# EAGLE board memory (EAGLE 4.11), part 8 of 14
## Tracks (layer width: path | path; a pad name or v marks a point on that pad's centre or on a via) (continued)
GND  (via drill 0.61) (continued)
  Bottom 0.635: B38.U2 29.84,288.93 26.04,288.93 24.13,290.83 21.59,290.83 20.32,289.56 17.78,289.56 B39.U2 | B38.N2 26.67,304.8 22.86,304.8 20.95,302.9 19.05,302.9 17.78,304.17 14.61,304.17 B39.N2 | B31.H2 119.38,321.31 120.02,321.95 124.46,321.95 125.09,322.58 127,322.58 128.91,320.68 131.44,320.68 B30.H2 | B35.V2 65.41,285.12 66.67,283.85 76.2,283.85 77.47,285.12 B34.V2 | A29.P2 144.78,370.84 145.41,370.21 149.86,370.21 151.13,368.94 153.67,368.94 A28.R2 | A20.U2 259.08,358.14 259.71,357.5 264.16,357.5 264.8,356.87 266.7,356.87 267.97,358.14 271.14,358.14 A19.U2 | B19.N2 268.61,304.17 269.24,303.53 273.69,303.53 274.32,302.9 v276.23,302.9 276.86,302.9 278.13,304.17 280.67,304.17 B18.N2 | B19.U2 271.78,288.29 272.42,287.66 v276.23,287.66 276.86,287.66 277.5,287.02 279.4,287.02 280.67,288.29 283.85,288.29 B18.U2 | B18.H2 283.85,320.04 283.21,319.41 278.76,319.41 278.13,318.77 275.59,318.77 274.32,320.04 271.78,320.04 B19.H2 | D03.C2 474.35,196.22 469.9,196.22 468.63,194.94 466.09,194.94 464.82,196.22 462.28,196.22 D04.C2 461.64,196.85 459.11,196.85 457.2,194.94 455.3,194.94 454.66,195.58 450.21,195.58 449.58,196.22 D05.C2 448.94,196.22 448.31,195.58 443.87,195.58 443.23,194.94 442.6,194.94 440.69,196.85 436.88,196.85 D06.C2 436.25,196.22 435.61,195.58 431.17,195.58 430.53,194.94 427.99,194.94 426.72,196.22 424.18,196.22 D07.C2 423.55,196.22 420.37,196.22 419.1,194.94 417.19,194.94 415.29,196.85 411.48,196.85 D08.C2 410.85,196.85 407.67,196.85 405.76,194.94 404.5,194.94 402.59,196.85 398.78,196.85 D09.C2 398.14,196.85 394.33,196.85 392.43,194.94 391.8,194.94 389.89,196.85 386.08,196.85 D10.C2 385.44,196.85 382.9,196.85 381,194.94 379.1,194.94 377.19,196.85 373.38,196.85 D11.C2 372.75,196.85 368.94,196.85 367.03,194.94 366.39,194.94 364.49,196.85 360.68,196.85 D12.C2 360.05,196.85 357.5,196.85 355.6,194.94 353.69,194.94 351.79,196.85 347.98,196.85 D13.C2 347.35,196.85 344.81,196.85 342.9,194.94 341,194.94 339.09,196.85 335.28,196.85 D14.C2 334.64,196.85 332.11,196.85 330.2,194.94 328.3,194.94 326.39,196.85 322.58,196.85 D15.C2 321.94,196.85 318.13,196.85 316.23,194.94 315.6,194.94 313.69,196.85 309.88,196.85 D16.C2 309.25,196.85 306.7,196.85 304.8,194.94 302.89,194.94 302.26,195.58 297.81,195.58 297.18,196.22 D17.C2 296.55,196.22 295.91,195.58 291.46,195.58 290.83,194.94 290.19,194.94 288.29,196.85 284.48,196.85 D18.C2 283.85,196.85 280.04,196.85 278.13,194.94 275.59,194.94 274.32,196.22 271.78,196.22 D19.C2 271.14,197.48 267.97,197.48 266.7,198.75 262.89,198.75 262.25,198.12 259.71,198.12 259.08,197.48 D20.C2 258.44,196.22 257.81,195.58 253.37,195.58 252.73,194.94 252.09,194.94 250.82,196.22 246.38,196.22 D21.C2 245.75,196.22 242.57,196.22 241.3,194.94 239.4,194.94 237.49,196.85 233.68,196.85 D22.C2 233.04,197.48 229.87,197.48 228.6,198.75 226.69,198.75 224.79,196.85 220.98,196.85 D23.C2 220.34,197.48 217.17,197.48 215.9,198.75 214,198.75 212.09,196.85 208.28,196.85 D24.C2 207.65,197.48 204.47,197.48 203.2,198.75 201.29,198.75 199.39,196.85 195.58,196.85 D25.C2 194.94,197.48 191.77,197.48 190.5,198.75 188.59,198.75 186.69,196.85 182.88,196.85 D26.C2 182.25,197.48 179.07,197.48 177.8,198.75 175.9,198.75 173.99,196.85 170.18,196.85 D27.C2 169.54,197.48 168.91,198.12 164.47,198.12 163.83,198.75 161.29,198.75 160.02,197.48 157.48,197.48 D28.C2 156.84,196.85 154.31,196.85 152.4,194.94 150.5,194.94 149.86,195.58 145.41,195.58 144.78,196.22 D29.C2 144.15,196.85 140.34,196.85 138.43,194.94 137.79,194.94 135.89,196.85 132.08,196.85 D30.C2 131.44,196.22 130.81,195.58 126.36,195.58 125.73,194.94 123.19,194.94 121.92,196.22 119.38,196.22 D31.C2 118.75,196.22 115.57,196.22 114.3,194.94 112.39,194.94 111.76,195.58 107.31,195.58 106.68,196.22 D32.C2 106.05,196.22 105.41,195.58 100.97,195.58 100.33,194.94 97.79,194.94 96.52,196.22 93.98,196.22 D33.C2 93.34,196.22 92.71,195.58 88.27,195.58 87.63,194.94 85.09,194.94 83.82,196.22 81.28,196.22 D34.C2 80.64,196.22 80.01,195.58 75.56,195.58 74.93,194.94 72.39,194.94 71.12,196.22 68.58,196.22 D35.C2 67.94,196.22 67.31,195.58 62.87,195.58 62.23,194.94 59.69,194.94 58.42,196.22 55.88,196.22 D36.C2 55.24,196.22 54.61,195.58 50.16,195.58 49.53,194.94 46.99,194.94 45.72,196.22 43.18,196.22 D37.C2 42.55,197.48 38.1,197.48 36.83,198.75 34.29,198.75 33.66,198.12 29.21,198.12
  Bottom 0.635: D10.H2 386.08,183.51 386.71,182.88 391.16,182.88 391.8,182.25 393.06,182.25 394.97,184.15 398.14,184.15 D09.H2 | C38.N2 27.3,237.49 31.75,237.49 33.02,236.22 35.56,236.22 36.83,237.49 39.37,237.49 C37.N2 | C22.U2 233.04,222.25 231.14,222.25 230.5,222.88 230.5,224.79 C22.T2 | v355.6,98.42 360.05,98.42 E12.P2 | F03.C2 474.35,59.69 473.71,59.05 469.26,59.05 468.63,58.42 466.09,58.42 464.82,59.69 462.28,59.69 F04.C2 461.64,59.69 461.01,59.05 456.56,59.05 455.93,58.42 453.39,58.42 452.12,59.69 449.58,59.69 F05.C2 448.94,59.69 448.31,59.05 443.87,59.05 443.23,58.42 440.69,58.42 439.42,59.69 436.88,59.69 F06.C2 436.25,60.96 431.8,60.96 430.53,62.23 427.99,62.23 426.72,60.96 424.18,60.96 F07.C2 423.55,60.96 422.91,61.59 418.46,61.59 417.83,62.23 415.29,62.23 414.02,60.96 411.48,60.96 F08.C2 410.85,60.96 410.21,61.59 405.76,61.59 405.13,62.23 402.59,62.23 401.32,60.96 398.78,60.96 F09.C2 398.14,59.69 397.51,59.05 393.06,59.05 392.43,58.42 389.89,58.42 388.62,59.69 386.08,59.69 F10.C2 385.44,59.69 382.27,59.69 381,58.42 379.1,58.42 377.19,60.33 373.38,60.33 F11.C2 372.75,59.69 369.57,59.69 368.3,58.42 366.39,58.42 364.49,60.33 360.68,60.33 F12.C2 360.05,59.69 356.87,59.69 355.6,58.42 353.69,58.42 351.79,60.33 347.98,60.33 F13.C2 347.35,60.33 343.54,60.33 341.63,58.42 341,58.42 339.09,60.33 335.28,60.33 F14.C2 334.64,60.33 330.83,60.33 328.93,58.42 327.66,58.42 325.75,60.33 322.58,60.33 F15.C2 321.94,60.33 318.13,60.33 316.23,62.23 314.96,62.23 313.06,60.33 309.88,60.33 F16.C2 309.25,60.96 308.61,61.59 304.17,61.59 303.53,62.23 302.26,62.23 300.36,60.33 297.18,60.33 F17.C2 296.55,60.96 293.37,60.96 292.1,62.23 290.19,62.23 288.29,60.33 284.48,60.33 F18.C2 283.85,60.96 283.21,61.59 278.76,61.59 278.13,62.23 276.86,62.23 274.95,60.33 271.78,60.33 F19.C2 271.14,60.33 267.33,60.33 265.43,58.42 262.89,58.42 261.62,59.69 259.08,59.69 F20.C2 258.44,60.33 254.63,60.33 252.73,58.42 250.19,58.42 248.92,59.69 246.38,59.69 F21.C2 245.75,59.69 245.11,59.05 240.66,59.05 240.03,58.42 237.49,58.42 236.22,59.69 233.68,59.69 F22.C2 233.04,60.33 229.24,60.33 223.52,54.61 220.98,54.61 F23.E2
  Bottom 0.635: F32.N2 103.5,32.38 104.14,33.02 108.58,33.02 113.03,37.46 115.57,37.46 F31.L2 | F31.C2 118.75,60.33 115.57,60.33 113.67,62.23 112.39,62.23 111.76,61.59 107.31,61.59 106.68,60.96 F32.C2 106.05,60.96 105.41,61.59 100.97,61.59 100.33,62.23 97.79,62.23 96.52,60.96 93.98,60.96 F33.C2 93.34,59.69 90.17,59.69 88.9,58.42 87,58.42 86.36,59.05 81.92,59.05 81.28,59.69 F34.C2 80.64,59.69 80.01,59.05 75.56,59.05 74.93,58.42 73.66,58.42 71.75,60.33 68.58,60.33 F35.C2 67.94,60.96 67.31,61.59 62.87,61.59 62.23,62.23 59.69,62.23 58.42,60.96 55.88,60.96 F36.C2 55.24,60.96 54.61,61.59 50.16,61.59 49.53,62.23 46.99,62.23 45.72,60.96 43.18,60.96 F37.C2 42.55,59.69 41.91,59.05 37.47,59.05 36.83,58.42 34.29,58.42 33.02,59.69 30.48,59.69 F38.C2 29.84,60.96 29.21,61.59 24.77,61.59 24.13,62.23 21.59,62.23 20.32,60.96 17.78,60.96 F39.C2 17.14,60.96 13.97,60.96 12.7,62.23 10.79,62.23 10.16,61.59 5.71,61.59 5.08,60.96 F40.C2 | F30.F2 128.27,50.16 127.64,49.53 123.83,49.53 119.38,45.09 116.2,45.09 F31.J2 | F23.C2 220.34,59.69 217.17,59.69 215.9,58.42 214,58.42 213.36,59.05 208.91,59.05 208.28,59.69 F24.C2 207.65,59.69 204.47,59.69 203.2,58.42 201.29,58.42 199.39,60.33 195.58,60.33 F25.C2 194.94,60.96 191.77,60.96 190.5,62.23 188.59,62.23 186.69,60.33 182.88,60.33 F26.C2 182.25,60.96 181.61,61.59 177.16,61.59 176.53,62.23 173.99,62.23 172.72,60.96 170.18,60.96 F27.C2 169.54,60.96 166.37,60.96 165.1,62.23 163.19,62.23 162.56,61.59 158.12,61.59 157.48,60.96 F28.C2 156.84,60.96 153.67,60.96 152.4,62.23 150.5,62.23 148.59,60.33 144.78,60.33 F29.C2
  Bottom 0.635: E03.C2 474.35,129.54 473.71,128.91 469.26,128.91 468.63,128.27 468,128.27 466.09,130.18 462.28,130.18 E04.C2 461.64,130.81 458.47,130.81 457.2,132.08 455.3,132.08 453.39,130.18 449.58,130.18 E05.C2 448.94,130.81 445.77,130.81 444.5,132.08 442.6,132.08 440.69,130.18 436.88,130.18 E06.C2 436.25,130.81 433.07,130.81 431.8,132.08 429.89,132.08 427.99,130.18 424.18,130.18 E07.C2 423.55,130.81 422.91,131.44 418.46,131.44 417.83,132.08 416.56,132.08 414.65,130.18 411.48,130.18 E08.C2 410.85,130.18 407.67,130.18 405.76,128.27 404.5,128.27 403.86,128.91 399.42,128.91 398.78,129.54 E09.C2 398.14,130.81 394.97,130.81 393.7,132.08 391.8,132.08 389.89,130.18 386.08,130.18 E10.C2 385.44,130.81 382.27,130.81 381,132.08 379.1,132.08 377.19,130.18 373.38,130.18 E11.C2 372.75,130.81 369.57,130.81 368.3,132.08 366.39,132.08 364.49,130.18 360.68,130.18 E12.C2 360.05,130.81 356.87,130.81 355.6,132.08 353.69,132.08 351.79,130.18 347.98,130.18 E13.C2 347.35,130.81 344.17,130.81 342.9,132.08 341,132.08 339.09,130.18 335.28,130.18 E14.C2 334.64,130.81 334.01,131.44 329.56,131.44 328.93,132.08 326.39,132.08 325.12,130.81 322.58,130.81 E15.C2 321.94,130.81 318.77,130.81 317.5,132.08 315.6,132.08 313.69,130.18 309.88,130.18 E16.C2 309.25,130.81 306.07,130.81 304.8,132.08 302.89,132.08 300.99,130.18 297.18,130.18 E17.C2 296.55,130.81 293.37,130.81 292.1,132.08 290.19,132.08 288.29,130.18 284.48,130.18 E18.C2 283.85,130.81 280.67,130.81 279.4,132.08 277.5,132.08 275.59,130.18 271.78,130.18 E19.C2 271.14,130.81 267.97,130.81 266.7,132.08 264.8,132.08 262.89,130.18 259.08,130.18 E20.C2 258.44,130.81 255.27,130.81 254,132.08 252.09,132.08 250.19,130.18 246.38,130.18 E21.C2 245.75,130.81 242.57,130.81 241.3,132.08 239.4,132.08 237.49,130.18 233.68,130.18 E22.C2 233.04,130.81 229.87,130.81 228.6,132.08 226.69,132.08 224.79,130.18 220.98,130.18 E23.C2 220.34,130.81 217.17,130.81 215.9,132.08 214,132.08 212.09,130.18 208.28,130.18 E24.C2 207.65,130.18 203.84,130.18 201.93,132.08 200.66,132.08 198.75,130.18 195.58,130.18 E25.C2 194.94,130.81 191.77,130.81 190.5,132.08 188.59,132.08 186.69,130.18 182.88,130.18 E26.C2 182.25,130.81 181.61,131.44 177.16,131.44 176.53,132.08 175.26,132.08 173.35,130.18 170.18,130.18 E27.C2 169.54,130.18 165.74,130.18 163.83,128.27 161.29,128.27 160.02,129.54 157.48,129.54 E28.C2 156.84,130.81 156.21,131.44 151.76,131.44 151.13,132.08 148.59,132.08 147.32,130.81 144.78,130.81 E29.C2 144.15,130.81 143.51,131.44 139.06,131.44 138.43,132.08 135.89,132.08 134.62,130.81 132.08,130.81 E30.C2
  Bottom 0.635: D09.U2 398.14,152.4 394.33,152.4 392.43,150.5 391.16,150.5 389.25,152.4 386.08,152.4 D10.U2 | D09.N2 394.97,167.64 394.33,167 389.89,167 389.25,166.37 387.99,166.37 386.08,168.28 382.9,168.28 D10.N2 | D40.C2 5.08,197.48 7.62,197.48 8.89,198.75 11.43,198.75 12.06,198.12 16.51,198.12 17.14,197.48 D39.C2 17.78,197.48 20.32,197.48 21.59,198.75 24.13,198.75 24.77,198.12 29.21,198.12 | 29.21,198.12 29.84,197.48 D38.C2 | E40.N2 1.91,100.96 5.08,100.96 9.53,96.52 13.34,96.52 13.97,95.88 E39.R2 14.61,95.88 17.78,95.88 23.5,101.6 26.67,101.6 E38.N2 | E32.U2 106.68,85.09 107.31,84.45 111.76,84.45 112.39,83.82 114.3,83.82 115.57,85.09 118.75,85.09 E31.U2 119.38,85.09 120.02,84.45 124.46,84.45 125.09,83.82 127,83.82 128.27,85.09 131.44,85.09 E30.U2 | E32.N2 103.5,100.96 104.14,100.33 108.58,100.33 109.22,99.69 111.76,99.69 113.03,100.96 115.57,100.96 E31.N2 | F39.N2 14.61,31.12 15.24,30.48 19.68,30.48 20.32,29.84 22.86,29.84 24.13,31.12 26.67,31.12 F38.N2 27.3,31.12 30.48,31.12 31.75,29.84 33.66,29.84 34.29,30.48 38.73,30.48 39.37,31.12 F37.N2 | E37.C2 43.18,130.81 45.72,130.81 46.99,132.08 49.53,132.08 50.16,131.44 54.61,131.44 55.24,130.81 E36.C2 55.88,130.81 58.42,130.81 59.69,132.08 62.23,132.08 62.87,131.44 67.31,131.44 67.94,130.81 E35.C2 68.58,130.81 71.12,130.81 72.39,132.08 74.93,132.08 75.56,131.44 80.01,131.44 80.64,130.81 E34.C2 81.28,130.81 83.82,130.81 85.09,132.08 87.63,132.08 88.27,131.44 92.71,131.44 93.34,130.81 E33.C2 93.98,130.81 96.52,130.81 97.79,132.08 100.33,132.08 100.97,131.44 105.41,131.44 106.05,130.81 E32.C2 106.68,130.81 109.22,130.81 110.49,132.08 113.03,132.08 114.94,130.18 118.75,130.18 E31.C2
IAC+CMA  (via drill 0.61)
  Top 0.254: v223.52,327.03 225.43,325.12 v225.43,278.77 | v276.23,278.13 276.23,22.86 271.78,18.41 271.78,16.51 F19.U2 | v337.19,33.02 336.55,32.38 336.55,17.78 335.28,16.51 F14.U2
  Route2 0.254: v223.52,327.03 220.98,327.03 B23.E2
  Bottom 0.254: F19.U2 271.78,16.51 276.23,16.51 277.5,17.78 286.38,17.78 287.02,17.14 289.56,17.14 290.19,17.78 299.08,17.78 299.72,17.14 302.26,17.14 302.89,17.78 311.79,17.78 312.42,17.14 314.96,17.14 315.6,17.78 324.49,17.78 325.12,17.14 327.66,17.14 328.3,17.78 329.56,17.78 330.83,16.51 334.64,16.51 F14.U2 | v225.43,278.77 275.59,278.77 v276.23,278.13 | v337.19,33.02 332.74,33.02 332.11,32.38 F14.N2
IF0  (via drill 0.61)
  Top 0.254: v122.56,67.94 122.56,78.1 116.84,83.82 116.84,87.63 116.2,88.27 E31.T2 | v258.44,39.37 266.7,31.12 v266.7,15.88 | v328.93,12.06 330.83,10.16 v330.83,9.52
  Route2 0.254: v122.56,67.94 123.19,68.58 133.99,68.58 143.51,59.05 149.86,59.05 153.67,55.25 162.56,55.25 163.19,55.88 172.09,55.88 172.72,55.25 175.26,55.25 175.9,55.88 184.78,55.88 185.42,55.25 187.96,55.25 188.59,55.88 197.49,55.88 201.29,52.07 210.19,52.07 210.82,52.7 213.36,52.7 216.53,49.53 222.88,49.53 229.87,42.55 238.76,42.55 239.4,43.18 246.38,43.18 250.19,39.37 v258.44,39.37
  Route3 0.254: v330.83,9.52 332.74,7.62 347.35,7.62 347.98,6.98 351.15,6.98 353.06,8.89 370.2,8.89 371.48,10.16 386.08,10.16 386.08,8.89 386.71,8.25 v386.71,7.62
  Bottom 0.254: v266.7,15.88 267.97,14.61 276.86,14.61 280.67,10.79 288.93,10.79 292.74,14.61 302.26,14.61 302.89,13.97 311.79,13.97 312.42,14.61 314.96,14.61 318.77,10.79 327.02,10.79 328.3,12.06 v328.93,12.06 | v386.71,7.62 387.99,6.35 393.7,6.35 394.33,6.98 401.32,6.98 405.13,10.79 435.61,10.79 445.77,20.95 454.66,20.95 458.47,17.14 467.36,17.14 468,17.78 476.88,17.78 477.52,17.14 479.43,17.14 498.48,36.2 498.48,39.37 491.49,39.37 487.05,43.82 484.5,43.82 F02.J2
IF1  (via drill 0.61)
  Top 0.254: v365.12,22.23 365.12,17.14 v354.96,6.98 | v336.55,4.44 330.83,4.44 327.02,0.63 288.93,0.63 v288.93,28.58 | v119.38,62.87 116.2,66.04 116.2,81.91 E31.V2
  Route2 0.254: v478.79,45.72 478.15,46.36 470.54,46.36 466.73,42.55 456.56,42.55 455.93,43.18 454.66,43.18 448.31,36.83 440.69,36.83 440.06,36.2 431.17,36.2 430.53,36.83 427.99,36.83 424.18,33.02 415.29,33.02 408.94,39.37 402.59,39.37 398.78,43.18 391.16,43.18 387.35,39.37 381,39.37 v376.56,34.92 | v354.96,6.98 352.43,4.44 341,4.44 339.73,5.71 337.82,5.71 v336.55,4.44 | v265.43,24.13 262.89,24.13 262.25,23.49 253.37,23.49 249.56,27.3 240.66,27.3 236.85,23.49 234.31,23.49 231.14,26.67 224.79,26.67 224.16,27.3 219.71,27.3 219.07,26.67 212.09,26.67 211.46,27.3 202.56,27.3 198.75,23.49 197.49,23.49 194.31,26.67 186.69,26.67 182.88,30.48 173.99,30.48 170.18,26.67 161.29,26.67 160.66,27.3 151.76,27.3 151.13,26.67 149.86,26.67 120.65,55.88 120.65,62.87 v119.38,62.87
  Route3 0.254: v376.56,34.92 365.12,23.49 v365.12,22.23
  Bottom 0.254: v478.79,45.72 485.77,45.72 487.05,46.99 F02.H2 | v288.93,28.58 287.65,29.84 283.21,29.84 280.04,26.67 275.59,26.67 274.95,27.3 272.42,27.3 269.24,24.13 v265.43,24.13
IF2  (via drill 0.61)
  Top 0.254: v163.19,393.7 179.07,409.58 179.07,421 179.71,421.64 306.07,421.64 v306.07,415.93
  Route2 0.254: v306.07,415.93 319.4,415.93 321.94,413.39 393.7,413.39 v396.24,415.93 | v506.1,249.56 504.82,248.28 504.82,67.94 499.11,67.94 484.5,53.34 484.5,51.44 F02.F2
  Route3 0.254: v114.3,158.75 114.3,151.76 107.95,145.41 107.95,121.92 104.78,118.74 104.78,90.8 103.5,89.53 E32.T2 | v122.56,165.1 123.83,166.37 123.83,203.2 122.56,204.47 122.56,217.17 123.83,218.44 123.83,316.87 127,320.04 127,356.24 163.19,392.43 v163.19,393.7
  Bottom 0.254: v114.3,158.75 114.3,163.83 121.28,163.83 v122.56,165.1 | v396.24,415.93 396.88,415.29 407.04,415.29 407.67,414.66 437.51,414.66 438.15,415.29 440.06,415.29 442.6,412.75 481.33,412.75 504.82,389.25 504.82,297.81 503.56,296.55 503.56,294 504.82,292.74 504.82,252.73 506.1,251.46 v506.1,249.56
INH1  (via drill 0.61)
  Top 0.254: v102.23,284.48 104.78,281.94 104.78,264.16 107.95,260.99 107.95,255.91 111.12,252.73 v111.12,244.47 | v156.84,239.39 156.21,238.76 156.21,238.12 158.75,235.59 158.75,229.23 161.93,226.06 v161.93,217.17
  Route2 0.254: v102.23,284.48 99.06,287.66 90.81,287.66 90.81,291.47 B33.T2 | v161.93,217.17 163.83,215.26 219.07,215.26 220.98,217.17 229.24,217.17 229.87,217.81 234.95,217.81 236.85,215.9 237.49,215.9 243.21,221.61 245.75,221.61 C21.U2
  Bottom 0.254: v111.12,244.47 113.67,244.47 118.11,240.03 120.65,240.03 121.28,240.66 123.83,240.66 125.09,239.39 132.72,239.39 133.99,240.66 136.53,240.66 137.79,239.39 146.69,239.39 147.32,240.03 149.86,240.03 150.5,239.39 v156.84,239.39
INHIBIT  (via drill 0.61)
  Top 0.254: v101.6,43.18 98.42,46.36 98.42,81.91 101.6,85.09 101.6,150.5 103.5,152.4 v103.5,153.67
  Route2 0.254: v103.5,153.67 121.92,172.09 123.83,172.09 128.27,176.53 134.62,176.53 138.43,180.34 140.97,180.34 D29.J2
  Bottom 0.254: v101.6,43.18 106.05,43.18 106.05,46.99 F32.H2
INS  (via drill 0.61)
  Top 0.254: v120.65,254 120.65,283.85 113.67,290.83 v113.67,294
  Route2 0.254: v81.28,175.89 85.09,179.7 93.34,179.7 99.69,186.06 108.58,186.06 109.22,185.42 109.86,185.42 v118.75,194.31 | v155.57,386.08 156.21,385.45 162.56,385.45 163.19,386.08 172.09,386.08 172.72,385.45 174.62,385.45 180.97,391.8 186.06,391.8 191.77,397.51 191.77,399.42 A25.D2
  Route3 0.254: v118.75,194.31 120.65,196.22 120.65,215.9 118.11,218.44 118.11,219.07 120.65,221.61 120.65,237.49 119.38,238.76 119.38,239.39 120.65,240.66 v120.65,254 | v113.67,294 117.47,297.81 117.47,341.63 126.36,350.52 126.36,356.87 133.35,363.86 133.35,369.57 149.86,386.08 v155.57,386.08
  Bottom 0.254: v81.28,175.89 74.93,175.89 62.23,163.19 61.59,163.19 60.96,163.83 52.07,163.83 41.27,153.03 40.01,154.31 36.2,154.31 35.56,153.67 28.57,153.67 27.3,154.94 D38.T2
IO_CLEAR  (via drill 0.61)
  Top 0.254: v277.5,57.15 279.4,55.25 279.4,27.3 280.67,26.03 F18.R2 | v295.91,76.2 295.27,75.56 295.27,61.59 v293.37,59.69 | v12.7,342.9 12.7,287.66 13.97,286.39 B39.V2 | v208.28,347.98 v208.28,351.16 | v295.27,367.67 295.27,379.1 294,380.37 A17.L2 | v170.18,154.94 170.18,156.84 171.45,158.11 171.45,167.64 168.28,170.81 v168.28,190.5 | v170.18,243.84 170.18,245.75 171.45,247.01 171.45,261.62 168.28,264.8 168.28,291.47 171.45,294.64 v171.45,306.07
  Route2 0.254: v379.1,88.9 370.84,80.64 350.52,80.64 349.25,79.38 312.42,79.38 311.15,78.1 297.81,78.1 v295.91,76.2 | v214.63,79.38 217.81,76.2 246.38,76.2 259.08,63.5 259.71,63.5 264.8,58.42 267.33,58.42 267.97,57.79 F19.D2
  Route3 0.254: v379.1,88.9 381,90.8 381,109.22 382.27,109.22 383.54,110.49 385.44,110.49 E10.K2 | v290.19,350.52 290.83,351.16 290.83,356.87 292.1,358.14 292.1,364.49 v295.27,367.67 | v198.75,79.38 196.85,81.28 v196.85,81.91 | v179.07,91.44 174.62,95.88 174.62,150.5 v170.18,154.94 | v168.28,190.5 168.28,218.44 171.45,221.61 171.45,242.57 v170.18,243.84 | v171.45,306.07 171.45,346.08 172.09,346.71 v172.09,347.98
  Bottom 0.254: F19.D2 268.61,57.79 269.88,59.05 275.59,59.05 v277.5,57.15 279.4,59.05 287.65,59.05 288.29,58.42 292.1,58.42 v293.37,59.69 | v12.7,342.9 98.42,342.9 102.23,346.71 133.35,346.71 133.99,346.08 166.37,346.08 168.28,347.98 v172.09,347.98 183.51,347.98 184.15,348.62 207.65,348.62 v208.28,347.98 | v208.28,351.16 208.91,351.79 210.82,351.79 212.09,350.52 223.52,350.52 224.16,351.16 247.01,351.16 248.28,349.89 249.56,349.89 250.19,350.52 269.88,350.52 271.14,349.25 288.93,349.25 v290.19,350.52 | v198.75,79.38 v214.63,79.38 | v196.85,81.91 194.94,83.82 186.69,83.82 v179.07,91.44
IO_INT  (via drill 0.61)
  Route2 0.254: v11.43,149.22 11.43,150.5 12.7,151.76 12.7,175.26 v14.61,177.16
  Route3 0.254: v11.43,149.22 9.53,147.32 9.53,125.09 6.35,121.92 6.35,43.18 5.08,41.91 F40.K2 | v14.61,177.16 15.88,178.44 15.88,224.79 22.23,231.14 22.23,276.23 25.4,279.4 25.4,299.09 28.57,302.26 28.57,344.81 22.23,351.16 22.23,368.3 23.5,369.57 19.05,374.02 19.05,391.16 8.26,401.96 1.91,401.96 1.91,400.69 A40.D2
ION  (via drill 0.61)
  Top 0.254: v23.5,127 25.4,128.91 25.4,140.97 24.13,142.24 24.13,150.5 25.4,151.76 25.4,156.84 27.94,159.38 27.94,160.66 28.57,161.29 v28.57,168.91 | v328.93,74.29 327.02,72.39 327.02,57.79 v330.2,54.61
  Route2 0.254: v328.93,74.29 331.47,76.83 350.52,76.83 351.15,77.47 353.69,77.47 354.33,76.83 377.82,76.83 379.73,78.74 405.76,78.74 408.31,81.28 409.57,81.28 409.57,87.63 423.55,101.6 423.55,104.14 E07.M2 | v330.2,54.61 325.75,59.05 325.12,59.05 321.94,55.88 316.23,55.88 313.06,59.05 310.51,59.05 307.98,56.52 307.98,50.16 v309.25,50.16 | v306.7,36.2 306.07,36.83 305.44,36.83 298.45,43.82 297.18,43.82 v296.55,43.18 | v283.85,38.1 282.57,39.37 279.4,39.37 275.59,35.56 273.05,35.56 272.42,36.2 266.06,36.2 259.08,43.18 250.19,43.18 249.56,42.55 248.28,42.55 245.11,45.72 237.49,45.72 231.14,52.07 226.69,52.07 224.16,54.61 222.25,54.61 218.44,58.42 212.09,58.42 211.46,59.05 202.56,59.05 201.93,58.42 199.39,58.42 195.58,62.23 186.69,62.23 182.88,58.42 173.99,58.42 170.18,62.23 161.29,62.23 160.66,61.59 153.03,61.59 v151.13,63.5
  Route3 0.254: v17.78,57.15 19.05,58.42 19.05,114.93 22.23,118.11 22.23,125.73 v23.5,127 | v28.57,168.91 28.57,179.07 27.3,180.34 D38.J2 | v309.25,50.16 311.15,48.26 311.15,40.64 v306.7,36.2 | v296.55,43.18 288.29,43.18 288.29,42.55 v283.85,38.1
  Bottom 0.254: 15.88,55.25 v17.78,57.15 | 15.88,55.25 3.81,43.18 1.91,43.18 1.91,38.73 F40.L2 | v151.13,63.5 149.86,63.5 147.96,61.59 141.6,61.59 135.25,55.25 127.64,55.25 125.09,57.79 119.38,52.07 110.49,52.07 109.86,52.7 100.97,52.7 100.33,52.07 97.79,52.07 93.98,55.88 85.09,55.88 84.45,55.25 75.56,55.25 71.75,59.05 62.87,59.05 59.05,55.25 50.16,55.25 49.53,55.88 46.99,55.88 43.18,52.07 34.29,52.07 30.48,55.88 21.59,55.88 20.95,55.25 15.88,55.25
IOP1  (via drill 0.61)
  Top 0.254: A40.T2 1.27,362.59 1.27,367.67 A40.R2 | v17.14,299.09 15.88,300.36 15.88,312.42 17.14,313.69 B39.K2 | v11.43,45.72 9.53,45.72 9.53,198.75 12.7,201.93 12.7,278.77 v11.43,280.04 | v415.93,5.08 v415.93,39.37 | v81.92,4.44 55.24,31.12 52.7,31.12 F36.N2 | v10.79,354.97 15.88,349.89 15.88,333.38 v14.61,332.11
  Route3 0.254: A40.J2 1.91,386.72 3.17,385.45 3.17,370.21 1.91,368.94 A40.R2
  Bottom 0.254: v17.14,299.09 8.26,290.2 5.71,290.2 5.08,289.56 B40.U2 5.08,288.29 5.08,286.39 v11.43,280.04 | v11.43,45.72 17.78,45.72 21.59,49.53 30.48,49.53 46.99,33.02 51.44,33.02 52.07,32.38 F36.N2 | v415.93,39.37 422.27,39.37 423.55,40.64 F07.K2 | v415.93,5.08 396.24,5.08 395.61,4.44 375.92,4.44 374.65,3.17 341,3.17 339.73,4.44 339.09,4.44 337.19,2.54 290.19,2.54 288.29,4.44 283.21,4.44 282.57,5.08 281.94,5.08 279.4,2.54 225.43,2.54 222.88,5.08 208.91,5.08 207.01,3.17 201.93,3.17 201.29,3.81 197.49,3.81 195.58,1.9 84.45,1.9 v81.92,4.44 | v10.79,354.97 5.71,360.05 3.17,360.05 1.91,361.31 A40.T2 | v14.61,332.11 19.68,327.03 19.68,325.12 15.88,321.31 15.88,314.96 17.14,314.96 B39.K2
IOP2  (via drill 0.61)
  Top 0.254: v377.82,368.94 374.65,372.11 374.65,388.62 373.38,389.89 A11.H2 | 3.17,294 1.91,292.74 B40.T2 | 3.17,306.71 3.17,379.1 1.91,380.37 A40.L2 1.91,381.64 1.91,383.54 6.35,387.99 6.35,407.04 6.99,407.67 6.99,415.93 v45.09,415.93 | 3.17,306.71 3.17,294 | v57.15,273.05 57.15,164.47 55.88,163.19 55.88,159.38 D36.S2 | v5.08,274.96 3.17,276.86 3.17,294 | 3.17,306.71 v1.91,306.71 | v331.47,412.12 331.47,412.75 347.98,412.75 365.12,395.61 365.12,387.99 369.57,387.99 A11.J2 | v261.62,417.2 257.81,417.2 254,421 180.34,421 v180.34,419.74
  Route2 0.254: v314.96,406.4 309.88,401.32 300.99,401.32 297.18,405.13 290.83,405.13 281.94,414.02 267.97,414.02 263.52,418.47 262.89,418.47 v261.62,417.2 | v180.34,419.74 177.8,417.2 150.5,417.2 149.22,415.93 v147.96,415.93
  Route3 0.254: v331.47,412.12 320.68,412.12 v314.96,406.4
  Bottom 0.254: A11.J2 370.2,387.99 372.11,389.89 372.75,389.89 A11.H2 | 407.04,360.68 407.04,358.78 407.67,358.14 407.67,356.24 A08.V2 | 407.04,360.68 408.94,360.68 410.85,362.59 410.85,364.49 A08.S2 | v377.82,368.94 380.37,366.4 391.16,366.4 391.8,367.03 399.42,367.03 405.76,360.68 407.04,360.68 | v57.15,273.05 57.15,274.96 v5.08,274.96 | v1.91,306.71 8.26,306.71 8.89,306.07 15.88,306.07 17.14,307.34 B39.M2 | v147.96,415.93 v45.09,415.93
IOP4  (via drill 0.61)
  Top 0.254: 34.92,332.11 v36.83,330.2 | 34.92,351.79 34.92,377.83 33.66,379.1 31.75,379.1 31.75,377.19 30.48,375.92 30.48,372.11 A38.P2 | 34.92,351.79 34.92,332.11 | v35.56,303.53 34.92,304.17 34.92,332.11 | v167,351.16 167,354.97 A27.V2 | v36.83,351.79 34.92,351.79
  Route2 0.254: v35.56,303.53 36.83,303.53 51.44,288.93 52.07,288.93 52.07,286.39 B36.V2
  Route3 0.254: v36.83,330.2 39.37,330.2 B37.D2
  Bottom 0.254: B40.S2 5.08,295.91 5.71,296.55 10.16,296.55 14.61,300.99 17.14,300.99 B39.P2 17.78,301.62 21.59,301.62 23.5,303.53 32.38,303.53 33.02,302.9 34.92,302.9 v35.56,303.53 | v167,351.16 130.18,351.16 128.91,352.43 37.47,352.43 v36.83,351.79 | A38.N2 27.3,374.02 29.21,372.11 29.84,372.11 A38.P2
IOT  (via drill 0.61)
  Top 0.254: v254.63,5.71 254,6.35 254,17.14 255.27,18.41 F20.T2 | v142.88,3.17 116.2,3.17 116.2,12.06 F31.V2 | v252.73,356.87 251.46,355.6 251.46,349.25 v252.09,348.62 | v210.82,350.52 210.82,338.46 206.38,334.01 v206.38,327.03 | v191.13,320.04 190.5,319.41 190.5,288.29 v186.69,284.48 | v90.81,118.11 88.9,116.2 v88.9,16.51
  Route2 0.254: v353.69,380.37 351.15,382.91 342.26,382.91 335.28,375.92 326.39,375.92 325.75,376.56 316.87,376.56 316.23,375.92 313.69,375.92 313.06,376.56 304.17,376.56 303.53,375.92 300.99,375.92 300.36,376.56 291.46,376.56 290.83,375.92 288.29,375.92 287.65,376.56 278.76,376.56 259.08,356.87 v252.73,356.87
  Route3 0.254: v370.2,383.54 370.2,381.64 A11.L2 | v106.68,284.48 98.42,276.23 98.42,235.59 95.25,232.41 95.25,156.21 92.08,153.03 92.08,119.38 v90.81,118.11
  Bottom 0.254: v370.2,383.54 375.92,389.25 378.46,389.25 379.1,388.62 387.99,388.62 388.62,389.25 391.16,389.25 391.8,388.62 400.69,388.62 401.32,389.25 403.86,389.25 404.5,388.62 413.38,388.62 421,396.24 423.55,396.24 A07.E2 | 88.9,10.79 114.3,10.79 115.57,12.06 F31.V2 | 88.9,10.79 20.32,10.79 10.16,20.95 1.91,20.95 1.91,24.77 F40.R2 | v254.63,5.71 253.37,4.44 227.97,4.44 226.69,5.71 208.28,5.71 206.38,3.81 202.56,3.81 201.93,4.44 196.85,4.44 194.94,2.54 143.51,2.54 v142.88,3.17 | v353.69,380.37 354.96,379.1 363.86,379.1 364.49,379.73 368.94,379.73 369.57,380.37 A11.L2 | v252.09,348.62 250.82,349.89 250.19,349.25 236.22,349.25 234.95,350.52 224.79,350.52 224.16,349.89 211.46,349.89 v210.82,350.52 | v206.38,327.03 205.1,325.75 202.56,325.75 198.75,321.95 193.04,321.95 v191.13,320.04 | v186.69,284.48 186.06,283.85 150.5,283.85 149.22,285.12 147.96,283.85 107.31,283.85 v106.68,284.48 | 88.9,10.79 v88.9,16.51
IR00  (via drill 0.61)
  Top 0.254: v255.91,165.73 254,167.64 254,175.89 255.27,177.16 255.27,180.34 D20.J2
  Route3 0.254: v289.56,167 292.1,169.54 292.1,175.26 295.91,179.07 295.91,182.88 296.55,183.51 D17.H2
  Bottom 0.254: v255.91,165.73 258.44,165.73 D20.P2 259.08,165.73 262.89,165.73 264.16,167 265.43,167 266.06,166.37 274.95,166.37 275.59,167 278.13,167 278.76,166.37 288.93,166.37 v289.56,167
IR01  (via drill 0.61)
  Top 0.254: v277.5,160.66 278.76,161.92 278.76,163.83 279.4,164.47 v279.4,186.69
  Route2 0.254: v277.5,160.66 271.14,154.31 264.8,154.31 264.16,153.67 257.18,153.67 255.91,154.94 D20.T2
  Bottom 0.254: D19.E2 271.78,189.86 276.23,189.86 v279.4,186.69 280.67,185.42 287.65,185.42 288.29,186.06 292.74,186.06 293.37,186.69 D17.F2
IR02  (via drill 0.61)
  Top 0.254: v268.61,165.1 266.7,167 266.7,176.53 267.97,177.8 267.97,180.34 D19.J2 | v271.78,168.28 271.78,165.73 D19.P2
  Route2 0.254: v268.61,165.1 271.14,165.1 D19.P2
  Bottom 0.254: v271.78,168.28 276.86,173.35 278.13,173.35 278.76,172.72 287.65,172.72 288.93,173.99 293.37,173.99 D17.L2
IR03  (via drill 0.61)
  Top 0.254: v407.67,415.93 409.57,414.02 409.57,402.59 410.21,401.96 410.21,398.15 410.85,397.51 A08.E2 | v322.58,415.93 320.68,414.02 320.68,401.96 319.4,400.69 A15.D2 318.77,399.42 317.5,398.15 317.5,392.43 320.68,389.25 320.68,382.91 v323.85,379.73 | v374.01,137.79 374.65,137.16 374.65,128.91 v372.75,127 | v267.33,375.92 266.7,375.29 266.7,356.24 264.8,354.33 v264.8,348.62
  Route2 0.254: v309.88,154.94 311.15,153.67 314.96,153.67 315.6,154.31 v317.5,154.31 | v347.98,154.31 354.96,147.32 365.12,147.32 v366.39,148.59 | v323.85,379.73 316.87,379.73 315.6,381 314.96,381 313.06,379.1 304.17,379.1 303.53,379.73 300.99,379.73 300.36,379.1 291.46,379.1 290.83,379.73 290.19,379.73 v288.93,378.46 | v262.25,307.98 v267.97,313.69 | v259.08,160.66 263.52,156.21 267.97,156.21 D19.T2
  Route3 0.254: v366.39,148.59 370.2,144.78 370.2,140.97 373.38,137.79 v374.01,137.79 | v264.8,348.62 265.43,347.98 265.43,341.63 266.7,340.36 266.7,320.04 265.43,318.77 265.43,316.23 v267.97,313.69 | v262.25,307.98 263.52,306.71 263.52,245.11 266.7,241.94 266.7,214 v261.62,208.91 | v255.91,208.91 254,207.01 254,178.44 257.18,175.26 257.18,162.56 v259.08,160.66
  Bottom 0.254: v407.67,415.93 405.76,417.83 327.02,417.83 325.12,415.93 v322.58,415.93 | v309.88,154.94 307.98,154.94 307.34,154.31 302.89,154.31 302.26,153.67 299.72,153.67 299.08,154.31 290.19,154.31 289.56,153.67 287.02,153.67 286.38,154.31 277.5,154.31 276.86,153.67 269.88,153.67 268.61,154.94 D19.T2 | v317.5,154.31 318.13,153.67 325.75,153.67 327.02,154.94 330.2,154.94 331.47,153.67 339.09,153.67 340.36,154.94 342.9,154.94 343.54,154.31 v347.98,154.31 | v372.75,127 370.2,127 E11.D2 | v288.93,378.46 287.65,377.19 285.75,377.19 285.12,376.56 278.76,376.56 274.95,372.75 272.42,372.75 269.24,375.92 v267.33,375.92 | v255.91,208.91 v261.62,208.91
IR03*-A1  (via drill 0.61)
  Top 0.254: v266.7,165.1 266.7,162.56 263.52,159.38 v263.52,158.75
  Route2 0.254: v271.14,94.61 290.83,74.93 300.99,74.93 303.53,72.39 335.92,72.39 v336.55,73.02
  Route3 0.254: v266.7,165.1 266.7,175.26 269.88,178.44 269.88,203.84 279.4,213.36 279.4,257.81 295.27,273.69 295.27,287.02 296.55,288.29 B17.U2 | v263.52,158.75 262.25,157.48 263.52,156.21 263.52,144.78 262.25,143.51 262.25,135.25 263.52,133.99 263.52,124.46 v262.25,123.19 | v267.97,118.11 269.88,116.2 269.88,95.88 v271.14,94.61 | v336.55,73.02 338.45,71.12 338.45,65.41 339.73,64.13 339.73,40.64 343.54,36.83 346.07,36.83 346.07,42.55 344.81,43.82 F13.J2
  Bottom 0.254: v262.25,123.19 265.43,120.02 266.06,120.02 v267.97,118.11
IR03*A1  (via drill 0.61)
  Route2 0.254: v296.55,323.22 295.91,322.58 292.74,322.58 289.56,325.75 283.21,325.75 282.57,325.12 275.59,325.12 274.95,325.75 272.42,325.75 262.25,315.6 253.37,315.6 249.56,319.41 242.57,319.41 233.04,309.88 226.06,309.88 v217.81,301.62 | v203.2,259.72 201.93,258.44 199.39,258.44 198.75,259.08 189.87,259.08 183.51,252.73 177.16,252.73 v166.37,241.94 | v170.18,101.6 180.97,90.8 186.69,90.8 193.04,84.45 200.66,84.45 204.47,80.64 219.71,80.64 223.52,76.83 236.22,76.83 238.12,78.74 243.84,78.74 245.75,76.83 264.16,76.83 281.94,59.05 288.29,59.05 300.36,46.99 301.62,46.99 306.07,42.55 314.96,42.55 315.6,43.18 323.85,43.18 v331.47,35.56
  Route3 0.254: v296.55,323.22 295.27,321.95 295.27,313.06 294,311.79 B17.L2 | v217.81,301.62 215.9,299.72 215.9,283.21 203.2,270.51 v203.2,259.72 | v166.37,241.94 166.37,240.03 158.75,232.41 158.75,180.34 160.02,179.07 160.02,177.8 158.75,176.53 158.75,147.32 168.28,137.79 168.28,103.5 v170.18,101.6
  Bottom 0.254: v331.47,35.56 332.11,36.2 336.55,36.2 340.36,32.38 344.17,32.38 F13.N2
IR03B  (via drill 0.61)
  Top 0.254: v374.65,348.62 377.82,345.44 v377.82,138.43 | v390.52,137.16 v390.52,95.25 | E09.U2 398.14,86.36 396.88,87.63 396.88,93.34 395.61,94.61 E09.R2
  Route3 0.254: v283.85,346.71 282.57,347.98 282.57,360.05 281.31,361.31 A18.T2
  Bottom 0.254: v283.85,346.71 284.48,347.35 325.75,347.35 326.39,347.98 374.01,347.98 v374.65,348.62 | v377.82,138.43 389.25,138.43 v390.52,137.16 | v390.52,95.25 394.97,95.25 E09.R2
ISZ  (via drill 0.61)
  Top 0.254: v290.19,73.02 v290.19,68.58 | v293.37,73.02 294.64,74.29 v294.64,76.2 | v404.5,74.29 398.14,74.29 v398.14,82.55
  Route2 0.254: v294.64,76.2 297.81,79.38 309.88,79.38 311.15,80.64 316.87,80.64 317.5,80.01 346.07,80.01 353.69,87.63 362.58,87.63 363.22,86.99 365.76,86.99 367.03,88.27 369.57,88.27 E11.T2 370.2,89.53 374.01,89.53 378.46,93.98 386.71,93.98 v398.14,82.55 | v477.52,190.5 466.73,179.7 466.73,171.45 465.45,171.45 460.38,166.37 460.38,130.18 457.83,130.18 452.75,135.25 451.49,135.25 447.68,131.44 447.68,111.76 446.4,111.76 445.13,110.49 445.13,109.22 418.46,82.55 418.46,79.38 415.93,79.38 410.85,74.29 v404.5,74.29
  Route3 0.254: v267.97,53.34 260.35,45.72 260.35,45.09 255.91,45.09 F20.J2 | v283.85,57.79 288.93,62.87 288.93,67.31 v290.19,68.58 | v446.4,343.54 438.15,351.79 438.15,375.92 436.88,377.19 A06.M2 | v478.15,320.68 479.43,319.41 479.43,295.91 476.25,292.74 476.25,281.94 482.6,275.59 482.6,243.84 483.87,242.57 483.87,240.03 482.6,238.76 482.6,224.16 v483.87,222.88 | v480.69,219.07 480.06,218.44 480.06,210.19 476.25,206.38 476.25,191.77 v477.52,190.5
  Bottom 0.254: v267.97,53.34 269.88,55.25 276.86,55.25 277.5,55.88 281.94,55.88 v283.85,57.79 | v293.37,73.02 v290.19,73.02 | v446.4,343.54 450.21,343.54 450.85,344.17 472.44,344.17 488.95,327.66 488.95,322.58 480.06,322.58 v478.15,320.68 | v483.87,222.88 480.69,219.71 v480.69,219.07
ISZ+DCA+JMS  (via drill 0.61)
  Top 0.254: v163.19,317.5 v160.02,314.33
  Route2 0.254: v165.1,311.15 163.83,312.42 161.93,312.42 v160.02,314.33 | v169.54,335.28 170.18,334.65 175.26,334.65 179.07,338.46 187.96,338.46 191.77,334.65 200.66,334.65 201.29,335.28 210.19,335.28 210.82,334.65 213.36,334.65 214,335.28 222.88,335.28 223.52,334.65 226.06,334.65 226.69,335.28 235.59,335.28 236.22,334.65 238.76,334.65 245.11,341 251.46,341 252.09,341.63 265.43,341.63 268.61,338.46 276.86,338.46 277.5,337.82 v284.48,337.82
  Route3 0.254: v229.24,9.52 220.98,17.78 212.72,17.78 212.72,19.69 205.74,26.67 199.39,26.67 199.39,28.58 171.45,56.52 171.45,86.36 165.1,92.71 165.1,132.72 153.67,144.14 153.67,147.32 152.4,148.59 152.4,160.02 151.13,161.29 151.13,163.19 152.4,164.47 152.4,281.94 158.75,288.29 158.75,294 165.1,300.36 v165.1,311.15 | v163.19,317.5 168.28,322.58 168.28,334.01 v169.54,335.28 | v284.48,337.82 286.38,339.73 286.38,343.54 297.81,354.97 298.45,354.97 299.72,353.7 299.72,345.44 295.27,341 295.27,328.93 296.55,327.66 B17.E2
  Bottom 0.254: v229.24,9.52 230.5,10.79 249.56,10.79 250.19,11.43 260.99,11.43 261.62,10.79 263.52,10.79 263.52,16.51 264.8,17.78 265.43,17.78 266.06,17.14 274.95,17.14 276.23,18.41 280.67,18.41 F18.T2
JMP  (via drill 0.61)
  Top 0.254: v250.19,81.28 250.19,74.29 244.47,68.58 244.47,32.38 250.82,26.03 255.27,26.03 F20.R2 | v271.78,193.04 269.88,194.94 269.88,218.44 v271.78,220.34 | v408.31,358.78 406.4,356.87 406.4,323.85 v405.13,322.58 | v319.4,320.68 319.4,318.14 B15.J2
  Route2 0.254: v405.13,322.58 398.78,328.93 389.89,328.93 389.25,328.3 380.37,328.3 379.73,328.93 377.19,328.93 376.56,328.3 367.67,328.3 367.03,328.93 364.49,328.93 363.86,328.3 354.96,328.3 354.33,328.93 353.69,328.93 349.88,325.12 341.63,325.12 338.45,321.95 329.56,321.95 328.93,322.58 326.39,322.58 325.75,321.95 320.68,321.95 v319.4,320.68
  Route3 0.254: v271.14,83.18 273.05,85.09 273.05,191.77 v271.78,193.04 | v271.78,220.34 276.23,224.79 276.23,256.54 294,274.32 v294,277.5 | v309.25,276.86 314.32,281.94 314.32,289.56 316.87,292.1 316.87,294 317.5,294.64 317.5,315.6 318.77,316.87 B15.J2
  Bottom 0.254: v250.19,81.28 250.82,80.64 268.61,80.64 v271.14,83.18 | v294,277.5 294.64,276.86 302.89,276.86 303.53,277.5 308.61,277.5 v309.25,276.86 | v408.31,358.78 409.57,360.05 413.38,360.05 416.56,356.87 421.64,356.87 422.91,355.6 423.55,355.6 425.45,357.5 427.36,357.5 427.99,356.87 434.98,356.87 436.25,358.14 A06.U2
JMS  (via drill 0.61)
  Top 0.254: A10.M2 385.44,378.46 384.81,379.1 384.81,382.91 384.18,383.54 384.18,393.7 386.08,395.61 386.08,396.24 A10.E2 | v236.22,78.1 236.22,72.39 234.95,71.12 231.78,74.29 231.78,207.64 232.41,208.28 v232.41,211.45 | v431.8,273.05 v431.8,210.19 | v439.42,274.96 441.32,276.86 v441.32,365.12 | v417.19,394.97 422.27,394.97 422.27,417.2 425.45,420.37 434.98,420.37 434.98,367.67 436.25,366.4 436.25,365.76 A06.S2
  Route3 0.254: v236.22,78.1 241.94,72.39 241.94,66.67 250.82,57.79 250.82,32.38 255.27,32.38 F20.N2
  Bottom 0.254: v232.41,211.45 233.04,212.09 315.6,212.09 316.23,211.45 332.74,211.45 333.38,210.82 381,210.82 381.63,210.19 v431.8,210.19 | v431.8,273.05 433.7,274.96 v439.42,274.96 | v441.32,365.12 436.88,365.12 A06.S2 | v417.19,394.97 416.56,395.61 414.02,395.61 413.38,394.97 404.5,394.97 400.69,398.78 391.8,398.78 391.16,398.15 386.71,398.15 386.08,397.51 A10.E2
JMS+DCA+ISZ+OP2  (via drill 0.61)
  Top 0.254: v382.9,111.12 383.54,111.76 383.54,113.03 384.18,113.66 v384.18,120.65 | v308.61,140.97 307.98,141.6 v307.98,151.76 | v255.91,271.78 256.54,272.42 256.54,284.48 255.91,285.12 B20.V2
  Route2 0.254: v382.9,111.12 384.18,109.85 389.25,109.85 389.89,109.22 394.33,109.22 394.97,108.58 E09.L2 | v384.18,120.65 384.18,121.92 377.19,121.92 373.38,125.73 364.49,125.73 360.68,121.92 351.79,121.92 348.62,125.09 343.54,125.09 334.01,134.62 326.39,134.62 325.75,135.25 319.4,135.25 316.23,138.43 311.15,138.43 v308.61,140.97 | v307.98,151.76 305.44,154.31 303.53,154.31 301.62,156.21 301.62,166.37 291.46,166.37 287.65,170.18 282.57,170.18 272.42,180.34 v271.78,180.34
  Route3 0.254: v259.08,186.69 257.81,187.96 257.81,189.23 257.18,189.86 257.18,270.51 v255.91,271.78
  Bottom 0.254: B20.V2 255.27,286.39 255.27,288.29 254.63,288.93 254.63,290.2 257.81,290.2 258.44,289.56 B20.U2 | v271.78,180.34 269.88,182.25 264.8,182.25 260.35,186.69 v259.08,186.69
L  (via drill 0.61)
  Top 0.254: B23.K2 220.34,314.96 219.07,316.23 219.07,325.75 217.81,327.03 217.81,329.56 B23.D2 | v337.82,28.58 339.73,26.67 v339.73,3.17 | v462.92,4.44 466.73,8.25 466.73,37.46 471.17,41.91 471.17,43.82 F03.J2 | v493.39,148.59 493.39,138.43 492.12,137.16 492.12,114.3 493.39,113.03 495.3,113.03 v495.3,57.15 | v425.45,232.41 425.45,224.16 v427.36,222.25 | v436.25,220.34 435.61,219.71 435.61,209.55 436.25,208.91 436.25,205.1 434.98,203.84 v434.98,172.72 | v474.35,163.19 474.35,159.38 D03.S2
  Route2 0.254: v337.82,28.58 335.28,28.58 F14.P2 | v493.39,148.59 v487.68,154.31 | v236.85,301.62 238.76,299.72 248.28,299.72 252.09,303.53 260.99,303.53 264.8,299.72 273.69,299.72 274.32,300.36 276.86,300.36 280.67,296.55 289.56,296.55 290.19,297.18 297.18,297.18 304.17,290.2 314.96,290.2 315.6,290.83 324.49,290.83 325.12,290.2 327.66,290.2 328.3,290.83 328.93,290.83 v331.47,288.29 | v338.45,273.69 346.71,265.43 346.71,263.53 348.62,263.53 356.87,271.78 365.76,271.78 372.11,265.43 378.46,265.43 382.27,261.62 391.16,261.62 394.97,265.43 403.86,265.43 404.5,264.8 408.94,264.8 423.55,250.19 423.55,248.28 C07.K2
  Route3 0.254: v425.45,232.41 425.45,245.75 424.18,247.01 C07.K2 | v223.52,302.9 222.25,304.17 222.25,308.61 220.98,309.88 220.98,313.69 B23.K2 | v331.47,288.29 338.45,281.31 v338.45,273.69
  Bottom 0.254: v339.73,3.17 340.36,2.54 375.29,2.54 376.56,3.81 396.24,3.81 396.88,4.44 406.4,4.44 408.31,2.54 461.01,2.54 v462.92,4.44 | v487.68,154.31 481.33,154.31 478.15,157.48 475.62,157.48 474.98,158.11 D03.S2 | v495.3,57.15 494.03,55.88 491.49,55.88 485.14,49.53 478.79,49.53 474.35,45.09 471.81,45.09 F03.J2 | v427.36,222.25 429.26,220.34 v436.25,220.34 | v434.98,172.72 441.96,172.72 442.6,173.35 445.13,173.35 448.31,170.18 454.02,170.18 457.83,166.37 464.82,166.37 468,163.19 v474.35,163.19 | v223.52,302.9 226.06,302.9 226.69,303.53 229.24,303.53 232.41,300.36 234.95,300.36 236.22,301.62 v236.85,301.62
LD  (via drill 0.61)
  Top 0.254: v171.45,375.29 171.45,385.45 168.91,385.45 168.28,384.81 168.28,382.91 167,381.64 A27.L2 | v138.43,369.57 133.35,364.49 133.35,346.71 131.44,344.81 v131.44,342.9
  Route3 0.254: v113.67,342.9 111.12,340.36 v111.12,317.5
  Bottom 0.254: B35.J2 65.41,316.87 66.67,315.6 73.66,315.6 74.3,316.23 83.19,316.23 83.82,315.6 86.36,315.6 87,316.23 92.08,316.23 93.34,314.96 B33.K2 93.98,314.96 96.52,314.96 97.79,316.23 100.33,316.23 100.97,315.6 111.12,315.6 v111.12,317.5 | v171.45,375.29 169.54,373.38 165.74,373.38 165.1,374.02 161.93,374.02 160.66,372.75 151.76,372.75 151.13,373.38 148.59,373.38 147.96,372.75 143.51,372.75 140.34,369.57 v138.43,369.57 | v131.44,342.9 v113.67,342.9
LD(B)  (via drill 0.61)
  Top 0.254: v125.73,148.59 123.83,146.69 123.83,126.36 120.65,123.19 120.65,113.03 119.38,111.76 E31.K2 | v134.62,151.13 139.7,156.21 139.7,166.37 140.97,167.64 D29.N2
  Bottom 0.254: v125.73,148.59 128.27,151.13 v134.62,151.13
MA11  (via drill 0.61)
  Top 0.254: v328.3,44.45 330.2,42.55 v330.2,15.88
  Route2 0.254: v274.95,67.31 280.67,61.59 287.02,61.59 295.91,52.7 302.26,52.7 308.61,46.36 314.96,46.36 315.6,45.72 324.49,45.72 325.12,46.36 326.39,46.36 v328.3,44.45 | v361.31,14.61 365.76,14.61 366.39,13.97 375.29,13.97 375.92,14.61 378.46,14.61 379.1,13.97 379.73,13.97 381,15.24 385.44,15.24 F10.U2
  Route3 0.254: v261.62,86.99 274.95,73.66 v274.95,67.31
  Bottom 0.254: v261.62,86.99 259.08,86.99 259.08,91.44 E20.S2 | v330.2,15.88 331.47,14.61 340.36,14.61 341,13.97 349.88,13.97 350.52,14.61 353.06,14.61 353.69,13.97 360.68,13.97 v361.31,14.61
MA11B  (via drill 0.61)
  Top 0.254: v339.73,65.41 339.73,27.94 343.54,24.13 343.54,20.32 344.17,19.69 F13.T2 | v334.01,65.41 332.74,66.67 332.74,81.28 333.38,81.91 333.38,83.82 332.11,85.09 332.11,88.27 E14.T2 | v430.53,306.07 436.88,312.42 436.88,313.69 B06.K2 | v328.3,293.37 330.2,291.47 330.2,265.43 331.47,264.16 C14.D2
  Route2 0.254: v334.01,65.41 v339.73,65.41 | v379.1,304.8 377.19,302.9 367.67,302.9 360.68,309.88 351.79,309.88 347.98,306.07 342.9,306.07 v341.63,304.8
  Route3 0.254: 330.2,121.92 330.2,94.61 330.83,93.98 330.83,90.17 331.47,89.53 E14.T2 | 330.2,121.92 v332.11,123.82 | 330.2,121.92 330.2,139.06 333.38,142.24 333.38,183.51 330.2,186.69 330.2,261.62 331.47,262.89 C14.D2 | v382.9,300.36 379.1,304.17 v379.1,304.8 | v341.63,304.8 339.73,302.9 339.73,297.18 v337.82,295.28
  Bottom 0.254: v332.11,123.82 333.38,122.55 336.55,122.55 339.73,125.73 344.17,125.73 345.44,124.46 347.35,124.46 E13.E2 | v430.53,306.07 427.99,306.07 427.36,306.71 418.46,306.71 417.83,306.07 415.29,306.07 414.65,306.71 413.38,306.71 411.48,304.8 410.21,304.8 408.94,303.53 403.86,303.53 400.05,299.72 389.89,299.72 389.25,300.36 v382.9,300.36 | v337.82,295.28 335.92,293.37 v328.3,293.37
MB00  (via drill 0.61)
  Top 0.254: v109.22,260.35 114.3,265.43 114.3,272.42 v116.2,274.32 | v436.25,245.11 436.25,241.94 C06.M2
  Route2 0.254: v116.2,274.32 122.56,280.67 198.75,280.67 201.93,277.5 208.91,277.5 210.19,276.23 229.87,276.23 231.78,278.13 269.88,278.13 280.04,267.97 287.02,267.97 290.19,264.8 299.08,264.8 299.72,265.43 302.26,265.43 302.89,264.8 311.79,264.8 315.6,268.61 317.5,268.61 | 317.5,268.61 324.49,268.61 328.3,264.8 337.19,264.8 337.82,265.43 340.36,265.43 344.17,261.62 353.06,261.62 353.69,262.25 356.24,262.25 359.41,259.08 365.76,259.08 366.39,258.44 v372.75,258.44 | v424.18,257.18 v436.25,245.11 | v322.58,101.6 v328.3,95.88 | v317.5,267.97 317.5,268.61
  Route3 0.254: v344.81,59.05 342.9,60.96 342.9,73.66 341,75.56 v341,81.28 | v328.93,82.55 330.2,83.82 330.2,93.34 328.3,95.25 v328.3,95.88 | v322.58,101.6 320.68,103.5 320.68,123.19 317.5,126.36 317.5,137.16 316.23,138.43 316.23,150.5 320.68,154.94 320.68,182.25 318.13,184.78 318.13,186.06 314.32,189.86 314.32,205.1 316.23,207.01 316.23,220.34 317.5,221.61 v317.5,267.97
  Bottom 0.254: v109.22,260.35 107.31,258.44 99.69,258.44 99.06,259.08 91.44,259.08 88.27,262.25 87,262.25 83.19,258.44 74.3,258.44 73.66,259.08 71.12,259.08 70.48,258.44 61.59,258.44 60.96,259.08 56.52,259.08 55.88,259.72 C36.E2 | v372.75,258.44 373.38,259.08 378.46,259.08 379.1,258.44 387.99,258.44 388.62,259.08 391.16,259.08 391.8,258.44 400.69,258.44 401.32,259.08 403.86,259.08 404.5,258.44 413.38,258.44 414.02,259.08 416.56,259.08 417.19,258.44 422.91,258.44 v424.18,257.18 | v344.81,59.05 351.15,59.05 353.06,57.15 356.87,57.15 F12.D2 | v341,81.28 340.36,80.64 330.83,80.64 v328.93,82.55
MB01  (via drill 0.61)
  Top 0.254: v307.98,110.49 307.98,115.57 306.7,116.84 v306.7,118.74 | v311.15,181.61 311.15,184.78 310.51,185.42 308.61,185.42 308.61,187.32 311.15,189.86 311.15,207.01 307.98,210.19 v307.98,219.07
  Route2 0.254: v318.77,61.59 325.75,61.59 326.39,62.23 328.93,62.23 329.56,61.59 335.92,61.59 342.26,55.25 348.62,55.25 351.79,52.07 356.24,52.07 356.87,51.44 F12.F2
  Route3 0.254: v318.77,61.59 317.5,62.87 317.5,67.94 316.87,68.58 316.87,76.2 311.15,81.91 311.15,94.61 307.98,97.79 v307.98,110.49 | v306.7,118.74 307.98,120.02 307.98,140.34 307.34,140.97 307.34,147.95 307.98,148.59 307.98,150.5 306.7,151.76 306.7,153.67 311.15,158.11 v311.15,181.61 | v307.98,219.07 307.98,227.97 304.8,231.14 304.8,233.68 306.07,234.95 306.07,236.22 304.8,237.49 304.8,252.09 v306.07,253.36
  Bottom 0.254: C06.H2 436.25,253.36 434.98,252.09 429.89,252.09 426.08,255.91 417.19,255.91 416.56,255.27 414.02,255.27 413.38,255.91 404.5,255.91 403.86,255.27 401.32,255.27 400.69,255.91 391.8,255.91 391.16,255.27 388.62,255.27 387.99,255.91 379.1,255.91 378.46,255.27 375.92,255.27 375.29,255.91 366.39,255.91 365.76,255.27 358.14,255.27 354.96,252.09 353.69,252.09 349.88,255.91 341,255.91 340.36,255.27 337.82,255.27 337.19,255.91 328.3,255.91 327.66,255.27 322.58,255.27 321.94,255.91 315.6,255.91 314.96,255.27 307.98,255.27 v306.07,253.36 303.53,255.91 302.89,255.91 302.26,255.27 299.72,255.27 299.08,255.91 290.19,255.91 289.56,255.27 279.4,255.27 278.76,255.91 277.5,255.91 276.86,255.27 266.7,255.27 266.06,255.91 264.8,255.91 264.16,255.27 261.62,255.27 260.99,255.91 252.09,255.91 251.46,255.27 245.75,255.27 245.11,255.91 238.12,255.91 237.49,255.27 236.22,255.27 235.59,255.91 226.69,255.91 226.06,255.27 223.52,255.27 222.88,255.91 214,255.91 213.36,255.27 210.82,255.27 210.19,255.91 201.29,255.91 200.66,255.27 190.5,255.27 189.87,255.91 188.59,255.91 187.96,255.27 185.42,255.27 184.78,255.91 175.9,255.91 175.26,255.27 172.72,255.27 172.09,255.91 163.19,255.91 162.56,255.27 160.02,255.27 159.38,255.91 150.5,255.91 146.69,252.09 137.79,252.09 133.99,255.91 125.09,255.91 124.46,255.27 121.92,255.27 121.28,255.91 112.39,255.91 111.76,255.27 104.14,255.27 100.97,252.09 99.69,252.09 95.89,255.91 87,255.91 86.36,255.27 83.82,255.27 83.19,255.91 74.3,255.91 73.66,255.27 71.12,255.27 70.48,255.91 61.59,255.91 60.96,255.27 56.52,255.27 55.88,254.63 C36.H2
MB02  (via drill 0.61)
  Top 0.254: v223.52,78.1 224.16,77.47 v224.16,67.31
  Route2 0.254: v74.93,149.22 73.03,149.22 73.03,162.56 69.22,166.37 66.67,166.37 66.67,232.41 56.52,242.57 55.88,242.57 55.88,247.01 C36.K2 | v142.88,113.03 143.51,112.39 147.32,112.39 156.21,103.5 162.56,103.5 163.19,102.87 172.09,102.87 172.72,103.5 175.26,103.5 191.77,86.99 200.66,86.99 201.29,87.63 202.56,87.63 207.01,83.18 209.55,83.18 210.82,84.45 212.09,84.45 215.26,81.28 220.34,81.28 v223.52,78.1 | v224.16,67.31 226.69,64.77 227.97,64.77 229.87,66.67 231.14,66.67 232.41,65.41 237.49,65.41 v248.92,53.98 | v309.88,55.88 312.42,53.34 314.32,53.34 318.77,48.9 327.66,48.9 331.47,52.7 340.36,52.7 344.17,48.9 350.52,48.9 354.33,45.09 356.87,45.09 F12.J2 357.5,45.09 360.05,45.09 370.2,55.25 376.56,55.25 379.73,58.42 386.08,58.42 389.89,62.23 396.24,62.23 402.59,68.58 438.79,68.58 v439.42,69.22 | v463.55,170.81 462.28,169.54 457.2,169.54 450.85,163.19 450.85,146.69 v448.94,146.69
  Route3 0.254: v74.93,149.22 75.56,148.59 75.56,137.79 76.2,137.16 76.2,118.74 v83.82,111.12 | v463.55,170.81 466.73,173.99 466.73,178.44 469.9,181.61 469.9,202.56 475.62,208.28 475.62,220.98 474.98,221.61 C03.U2 | v448.94,146.69 447.68,145.41 447.68,77.47 v439.42,69.22
  Bottom 0.254: v83.82,111.12 88.9,116.2 99.06,116.2 102.87,112.39 111.76,112.39 112.39,113.03 121.28,113.03 121.92,112.39 124.46,112.39 125.09,113.03 133.99,113.03 134.62,112.39 137.16,112.39 137.79,113.03 v142.88,113.03 | v248.92,53.98 250.82,52.07 260.99,52.07 261.62,52.7 264.16,52.7 264.8,52.07 273.69,52.07 274.32,52.7 276.86,52.7 277.5,52.07 286.38,52.07 287.02,52.7 289.56,52.7 290.19,52.07 293.37,52.07 294,52.7 298.45,52.7 300.36,54.61 301.62,54.61 302.89,55.88 v309.88,55.88
MB03  (via drill 0.61)
  Top 0.254: v143.51,220.34 142.88,219.71 v142.88,214 | v172.72,210.19 173.35,209.55 v173.35,203.2
  Route2 0.254: v173.35,203.2 178.44,198.12 187.96,198.12 188.59,198.75 197.49,198.75 198.12,198.12 200.66,198.12 201.29,198.75 207.65,198.75 210.82,201.93 213.36,201.93 214,201.29 218.44,201.29 219.07,201.93 226.06,201.93 226.69,201.29 233.68,201.29 236.85,204.47 238.76,204.47 239.4,205.1 271.78,205.1 273.69,203.2 | 273.69,203.2 v278.13,198.75 | v462.28,212.09 467.36,217.17 473.71,217.17 480.69,224.16 480.69,226.06 474.98,231.78 474.98,234.31 C03.P2 | v436.88,209.55 436.25,210.19 434.98,210.19 433.7,208.91 392.43,208.91 391.16,210.19 313.06,210.19 311.15,208.28 297.18,208.28 295.91,209.55 283.85,209.55 282.57,208.28 278.76,208.28 273.69,203.2
  Route3 0.254: v53.98,307.34 55.24,306.07 55.24,303.53 53.98,302.26 53.98,259.72 57.15,256.54 57.15,220.34 v55.88,219.07 | v278.13,198.75 279.4,197.48 279.4,191.13 285.75,184.78 285.75,175.26 281.31,170.81 281.31,168.91 D18.N2
  Bottom 0.254: v53.98,307.34 48.26,313.06 43.81,313.06 43.18,313.69 B37.K2 | v55.88,219.07 57.78,217.17 83.19,217.17 84.45,215.9 116.84,215.9 118.11,217.17 135.25,217.17 138.43,220.34 v143.51,220.34 | v142.88,214 143.51,213.36 146.05,213.36 149.22,210.19 v172.72,210.19 | v462.28,212.09 461.01,210.82 454.66,210.82 452.75,208.91 452.12,209.55 v436.88,209.55
MB04  (via drill 0.61)
  Top 0.254: v439.42,170.18 438.15,171.45 438.15,211.45 436.88,212.72 v436.88,217.17 | v474.35,224.16 476.25,226.06 476.25,243.2 474.98,244.47 474.98,247.01 C03.K2 | v370.2,349.25 368.3,351.16 v368.3,363.86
